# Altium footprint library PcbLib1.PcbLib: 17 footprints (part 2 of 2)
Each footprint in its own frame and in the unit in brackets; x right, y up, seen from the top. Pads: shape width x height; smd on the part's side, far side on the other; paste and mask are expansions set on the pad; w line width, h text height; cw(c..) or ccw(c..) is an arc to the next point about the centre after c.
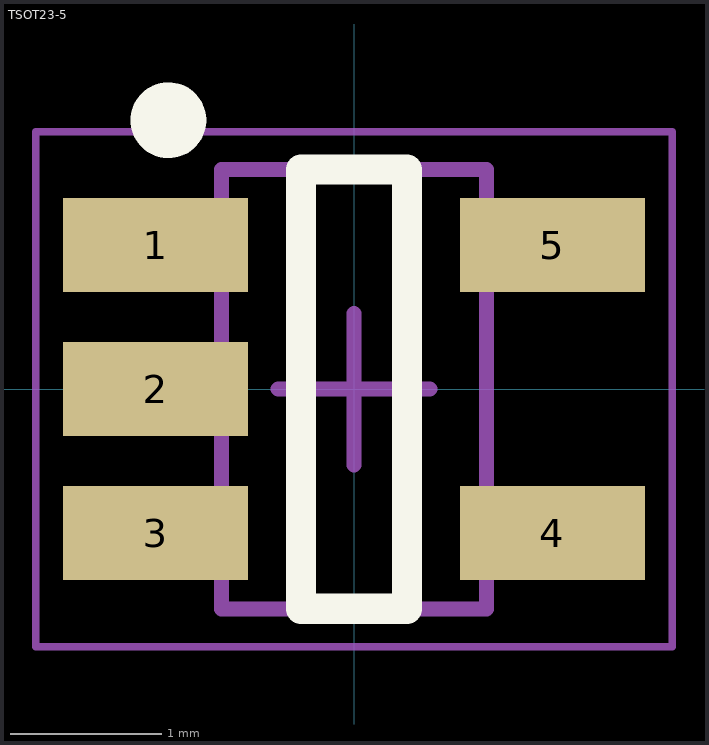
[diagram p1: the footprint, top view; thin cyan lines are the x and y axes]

## TSOT23-5 [mm] "SOT23, 5-Leads, Body 2.90x2.80mm, Pitch 0.95mm, IPC Medium Density"
height 1
pads (5):
  rect 1.22x0.62 smd: 1(-1.31,0.95) 2(-1.31,0) 3(-1.31,-0.95) 4(1.31,-0.95) 5(1.31,0.95)
Top Overlay:
  circle w0.25: c-1.225,1.775 r0.125
  lines w0.2: -0.35,-1.45 0.35,-1.45 0.35,1.45 -0.35,1.45 -0.35,-1.45
Mechanical 13:
  lines w0.1: -0.875,-1.45 -0.875,1.45 0.875,1.45 0.875,-1.45 -0.875,-1.45
Mechanical 15:
  lines w0.05: -2.1,-1.7 -2.1,1.7 2.1,1.7 2.1,-1.7 -2.1,-1.7
  lines w0.1: -0.5,0 0.5,0 ; 0,-0.5 0,0.5
3D body: height 1, standoff 0.01, extent -0.875,-1.45 0.875,1.45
